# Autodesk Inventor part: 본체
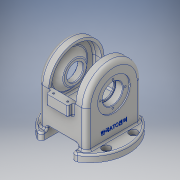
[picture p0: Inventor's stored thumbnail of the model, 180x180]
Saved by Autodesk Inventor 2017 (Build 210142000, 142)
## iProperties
Part Number: 본체
Material: 알루미늄 6061
Document SubType Name: Modeling
Designer: MRC
Density: 2.7 g/cm^3
Appearance: 알루미늄 - 평지
Mass: 1199.23 g
Surface Area: 1051.82 cm^2
Volume: 444.159 cm^3
Author: MRC
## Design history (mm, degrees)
sketch "스케치1"
  geometry: L1 (0, 0)-(0, -71); L2 (28, -65.246)-(28, 0); L3 (-28, -65.246)-(-28, 0); L4 (28, 0)-(28, 65.246); L5 (-28, 0)-(-28, 65.246); A1 r 71 centre (0, 0) between (0, -71) and (28, -65.246); 1 further point
  constraints: 10 end point, 5 point on circle, 3 vertical, 1 centre point, 1 coincident
  dimensions: "d0" = 142 diameter of A1; "d1" = 28 distance between parallel lines of L1 L2; "d2" = 28 distance between parallel lines of L1 L3
extrude "돌출1" new body sketch "스케치1" distance "d3" = 13; taper "d4" = 0 deg
fillet "모깎기1" dims "d5" = 6
sketch "스케치2"
  geometry: L1 (0, 0)-(81, 0); L2 (13, -60.512)-(0, -60.512) reference; L3 (13, 60.512)-(13, -60.512) reference; L4 (0, 60.512)-(13, 60.512) reference; L5 (0, 60.512)-(0, -60.512) reference; L6 (81, 0)-(81, 51); L7 (81, 51)-(13, 51); L8 (81, 0)-(81, -51); L9 (81, -51)-(13, -51); L10 (0, 51)-(0, -51); L11 (13, -60.512)-(13, 60.512) reference; L12 (13, 51)-(13, -51); A1 r 51 centre (81, 0) between (81, -51) and (81, 51)
  constraints: 14 end point, 5 point on line, 3 perpendicular, 2 point on circle, 1 centre point, 1 coincident, 1 horizontal, 1 vertical
  dimensions: "d6" = 81 distance of L1.start L1.end; "d7" = 102 diameter of A1
extrude "돌출2" join sketch "스케치2" stored distance "d8" = 88; taper "d9" = 0 deg
sketch "스케치3"
  geometry: L1 (-44, 81)-(44, 81) reference; L2 (44, 81)-(44, 81) reference; L3 (-44, 81)-(44, 81) reference; L4 (-44, 81)-(-44, 81) reference; L5 (-44, 81)-(44, 81) reference; L6 (44, 13)-(44, 81) reference; L7 (28, 13)-(44, 13) reference; L8 (-28, 13)-(28, 13) reference; L9 (-44, 13)-(-28, 13) reference; L10 (-44, 81)-(-44, 13) reference; L11 (-44, 81)-(44, 81) reference; L12 (0, 81)-(-25, 81); L13 (-25, 81)-(25, 81); L14 (25, 81)-(25, 141); L15 (25, 141)-(-25, 141); L16 (-25, 141)-(-25, 81); 1 further point
  constraints: 10 end point, 2 parallel, 1 coincident, 1 horizontal, 1 midpoint, 1 perpendicular, 1 point on line
  dimensions: "d15" = 25 distance of L12.start L12.end; "d16" = 50 distance of L15.end L14.end; "d17" = 60 distance of L14.end L13.end
extrude "돌출3" cut sketch "스케치3" stored distance "d18" = 146.5; taper "d19" = 0 deg
node "작업 평면1"
sketch "스케치5"
  geometry: L1 (39, 46)-(-39, 46); L2 (-39, 46)-(-39, -46); L3 (-39, -46)-(39, -46); L4 (39, -46)-(39, 46); L5 (39, 46)-(-39, -46); L6 (-39, 46)-(39, -46); 1 further point
  constraints: 12 end point, 2 midpoint, 2 parallel, 1 horizontal, 1 perpendicular
  dimensions: "d23" = 78 distance of L3.end L2.end; "d24" = 92 distance of L2.end L1.end
extrude "돌출4" cut sketch "스케치5" distance "d25" = 41; taper "d26" = 0 deg
sketch "스케치6"
  geometry: L1 (51, 0)-(51, -68) reference; L2 (-51, -68)-(51, -68) reference; L3 (-51, -68)-(-51, 0) reference; L4 (-51, 0)-(51, 0); L5 (46, -41)-(46, 0) reference; L6 (-46, 0)-(46, 0); L7 (46, 0)-(-46, 0) reference; L8 (0, 0)-(0, 46); A1 r 51 centre (0, 0) between (51, 0) and (-51, 0) reference; A2 r 46 centre (0, 0) between (46, 0) and (-46, 0); 1 further point
  constraints: 6 end point, 3 point on circle, 3 point on line, 1 centre point, 1 coincident, 1 collinear, 1 perpendicular, 1 vertical
  dimensions: "d28" = 46 distance of L8.start L8.end
extrude "돌출5" cut sketch "스케치6" distance "d29" = 14; taper "d30" = 0 deg
sketch "스케치7"
  geometry: C1 r 33.5 at (46, 41); A1 r 51 centre (46, 41) between (97, 41) and (-5, 41) reference; 1 further point
  constraints: 1 centre point, 1 coincident
  dimensions: "d31" = 67 diameter of C1
extrude "돌출6" join sketch "스케치7" distance "d32" = 12; taper "d33" = -45 deg
sketch "스케치8"
  geometry: C1 r 30 at (0, 81); A1 r 51 centre (0, 81) between (51, 81) and (-51, 81) reference; 1 further point
  constraints: 1 centre point, 1 coincident
  dimensions: "d34" = 60 diameter of C1
extrude "돌출7" cut sketch "스케치8" distance "d35" = 2; taper "d36" = 0 deg
sketch "스케치9"
  geometry: C1 r 30 at (0, 0) reference; C2 r 18.5 at (0, 0); 1 further point
  constraints: 1 centre point, 1 coincident
  dimensions: "d37" = 37 diameter of C2
extrude "돌출8" cut sketch "스케치9" distance "d38" = 13; taper "d39" = 0 deg
sketch "스케치10"
  geometry: C1 r 18.5 at (0, 0) reference; C2 r 16 at (0, 0); 1 further point
  constraints: 1 centre point, 1 coincident
  dimensions: "d40" = 32 diameter of C2
extrude "돌출9" cut sketch "스케치10" distance "d41" = 13; taper "d42" = 0 deg
sketch "스케치11"
  geometry: C1 r 30 at (28, 51); 1 further point
  constraints: 1 centre point, 1 coincident
  dimensions: "d43" = 60 diameter of C1
extrude "돌출10" cut sketch "스케치11" distance "d44" = 70.75; taper "d45" = 0 deg
sketch "스케치12"
  geometry: C1 r 30 at (28, 51); 1 further point
  constraints: 1 centre point, 1 coincident
  dimensions: "d46" = 60 diameter of C1
extrude "돌출11" cut sketch "스케치12" distance "d47" = 9; taper "d48" = 0 deg
sketch "스케치13"
  geometry: C1 r 14 at (0, 0); 1 further point
  constraints: 1 centre point, 1 coincident
  dimensions: "d49" = 28 diameter of C1
extrude "돌출12" cut sketch "스케치13" distance "d50" = 15; taper "d51" = 0 deg
sketch "스케치14"
  geometry: C1 r 11 at (0, 0); 1 further point
  constraints: 1 centre point, 1 coincident
  dimensions: "d52" = 22 diameter of C1
extrude "돌출13" cut sketch "스케치14" distance "d53" = 15; taper "d54" = 0 deg
sketch "스케치15" dims "d55" = 46
  geometry: L1 (0, 0)-(0, 23); C1 r 30 at (0, 0) reference; 2 further points
  constraints: 2 end point, 1 coincident, 1 vertical, 1 vertical alignment, 2 other
hole "구멍1" sketch "스케치15" at (0, 23) diameter "d56" = 3.242; stored, may be unused: countersink angle "d60" = 90 deg, drill point angle "d62" = 118 deg; dims "d57" = 8, "d58" = 4, "d59" = 2, "d61" = 10
node "작업 평면2"
sketch "스케치16"
  geometry: L1 (0, 0)-(0, -61); L2 (0, -61)-(20, -61); L3 (20, -61)-(20, -46); L4 (-39, -46)-(39, -46) reference; L5 (20, -46)-(-20, -46); L6 (-20, -46)-(-20, -61); L7 (-20, -61)-(0, -61)
  constraints: 12 end point, 3 perpendicular, 2 point on line, 1 horizontal, 1 vertical
  dimensions: "d67" = 61 distance of L1.start L1.end; "d68" = 20 distance of L1.end L2.end; "d69" = 40 distance of L3.end L5.end
extrude "돌출14" join sketch "스케치16" distance "d70" = 20; taper "d71" = 0 deg
sketch "스케치17"
  geometry: L1 (45, 0)-(50, 0) reference; L2 (50, 5)-(50, 0) reference; L3 (50, 5)-(0, 5) reference; L4 (0, 0)-(0, 5) reference; L5 (0, 0)-(5, 0) reference; L6 (5, -10)-(5, 0) reference; L7 (45, -10)-(5, -10) reference; L8 (45, 0)-(45, -10) reference; L9 (38, 105)-(12, 105); L10 (12, 105)-(12, -3); L11 (12, -3)-(38, -3); L12 (38, -3)-(38, 105); L13 (38, 105)-(12, -3); L14 (12, 105)-(38, -3); 5 further points
  constraints: 12 end point, 4 coincident, 2 midpoint, 2 parallel, 1 horizontal, 1 perpendicular
  dimensions: "d72" = 26 distance of L11.end L10.end; "d73" = 108 distance of L10.end L9.end
hole "구멍2" sketch "스케치17" at (12, -3), (38, -3), (12, 105), (38, 105) diameter "d74" = 3.242; stored, may be unused: countersink angle "d78" = 90 deg, drill point angle "d80" = 118 deg; dims "d75" = 8, "d76" = 4, "d77" = 2, "d79" = 10
sketch "스케치18"
  geometry: L1 (-55, 25)-(55, 25); L2 (55, 25)-(55, -25); L3 (55, -25)-(-55, -25); L4 (-55, -25)-(-55, 25); L5 (-55, 25)-(55, -25); L6 (55, 25)-(-55, -25); 5 further points
  constraints: 12 end point, 4 coincident, 2 midpoint, 2 parallel, 1 horizontal, 1 perpendicular
  dimensions: "d81" = 110 distance of L2.end L3.end; "d82" = 50 distance of L1.end L2.end
hole "구멍3" sketch "스케치18" at (55, -25), (55, 25), (-55, -25), (-55, 25) diameter "d83" = 9; stored, may be unused: countersink angle "d87" = 90 deg, drill point angle "d89" = 118 deg; dims "d84" = 8, "d85" = 15, "d86" = 8.8, "d88" = 10
fillet "모깎기2" dims "d90" = 0.3
chamfer "모따기1" distance "d91" = 1; stored, may be unused: second distance "d92" = 2, angle "d93" = 45 deg
fillet "모깎기3" dims "d94" = 3
fillet "모깎기4" dims "d95" = 3
fillet "모깎기5" dims "d96" = 8
fillet "모깎기9" dims "d100" = 3
sketch "스케치19" dims "d101" = 46
  geometry: L1 (0, 0)-(0, 23); 1 further point
  constraints: 2 end point, 1 coincident, 1 vertical, 1 vertical alignment, 2 other
hole "구멍4" sketch "스케치19" at (0, 23) diameter "d102" = 3.242; stored, may be unused: countersink angle "d106" = 90 deg, drill point angle "d108" = 118 deg; dims "d103" = 8, "d104" = 15, "d105" = 8.8, "d107" = 10
chamfer "모따기2" distance "d112" = 1; stored, may be unused: second distance "d113" = 2, angle "d114" = 45 deg
fillet "모깎기10" dims "d115" = 3
fillet "모깎기11" dims "d116" = 3
fillet "모깎기12" dims "d117" = 3
sketch "스케치20"
  geometry: L1 (60.512, 0)-(-60.512, 0) reference; 3 further points
  constraints: 1 midpoint, 1 vertical alignment, 1 other
  dimensions: "d118" = 30 distance from line of L1 point (0, 30)
feature "엠보싱1" sketch "스케치20" dims "d119" = 0.5, "d120" = 0
sketch "스케치22"
  geometry: L1 (0, 0)-(0, 19); L2 (-28, 0)-(-37.138, 0) reference; L3 (0, 0)-(-28, 0); L4 (-28, 0)-(-28, 19); L5 (-31, 16)-(31, 16) reference; L6 (-28, 19)-(0, 19)
  constraints: 8 end point, 1 horizontal, 1 parallel, 1 perpendicular, 1 vertical
  dimensions: "d123" = 19 distance of L1.start L1.end
revolve "회전1" sketch "스케치22" stored, may be unused: angle "d124" = 90 deg
sketch "스케치23"
  geometry: L1 (64, -71)-(73.138, -71) reference; L2 (64, -71)-(64, -81) reference; L3 (64, -81)-(73.138, -81) reference; L4 (73.138, -81)-(73.138, -71) reference; L5 (71.569, -68)-(67, -68) reference; L6 (64, -71)-(73.138, -71) reference; L7 (67, -68)-(67, -65) reference; L8 (36, -81)-(64, -81); L9 (64, -81)-(64, -62); L10 (64, -62)-(36, -62); L11 (36, -62)-(36, -81); L12 (8, -62)-(36, -62); L13 (36, -81)-(8, -81); L14 (8, -81)-(8, -62); A1 r 3 centre (67, -71) between (67, -68) and (64, -71) reference; 1 further point; 1 other entity
  constraints: 14 end point, 2 parallel, 2 symmetric about line, 1 horizontal, 1 perpendicular, 1 other
  dimensions: "d125" = 28 distance of L10.end L9.end; "d126" = 19 distance of L9.end L8.end
extrude "돌출16" cut sketch "스케치23" distance "d127" = 138.75; taper "d128" = 0 deg
fillet "모깎기13" dims "d129" = 3
fillet "모깎기14" dims "d130" = 3
fillet "모깎기15" dims "d131" = 3
node "솔리드1"
mirror "미러1"
mirror "미러2"
pattern_circular "원형 패턴1" dims angle "d64" = 360 deg
mirror "미러3"
mirror "미러4"
pattern_circular "원형 패턴2" dims angle "d110" = 360 deg
node "투영된 루프1"
node "투영된 루프2"
node "투영된 루프3"
node "투영된 루프4"
node "투영된 루프5"
node "투영된 루프7"
node "투영된 루프8"
other parameters: "d66" = 81
